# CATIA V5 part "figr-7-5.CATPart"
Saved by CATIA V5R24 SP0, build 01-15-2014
Part number: Part1
Bounding box of the stored display mesh (mm): x 0 to 95, y -20 to 20, z 0 to 40
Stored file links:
  D:\KAVITA\CATIA V5-6R2014 Project_ Kavita\CATIA V5-6R2014_partfiles\Partfiles\c07_catia_v5-6r2014_prt\figr-7-5.CATPart
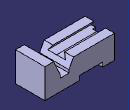
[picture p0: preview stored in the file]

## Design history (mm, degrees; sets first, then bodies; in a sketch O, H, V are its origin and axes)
Body1 (main body)
  Sketch1 on zx-plane, origin (0, 0, 0), H (-1, 0, 0), V (0, 0, 1)
    line L1 (0, 0) -> (-16, 0)
    line L2 (-16, 0) -> (-16, 6)
    line L3 (-16, 6) -> (-48, 6)
    line L4 (-48, 6) -> (-48, 0)
    point P4 (-48, 0)
    line L5 (-48, 0) -> (-95, 0)
    line L6 (-95, 0) -> (-95, 40)
    line L7 (-95, 40) -> (-83, 40)
    line L8 (-83, 40) -> (-74, 20)
    line L9 (-74, 20) -> (-74, 16)
    line L10 (-74, 16) -> (-62, 16)
    line L11 (-62, 16) -> (-62, 20)
    line L12 (-62, 20) -> (-56, 32)
    line L13 (-56, 32) -> (0, 32)
    line L14 (0, 32) -> (0, 0)
    length L1 = 16
    length L3 = 32
    length L13 = 56
    distance L14 L6 = 95
    length L14 = 32
    length L6 = 40
    length L12 H = 6
    length L10 = 12
    length L7 = 12
    length L9 = 4
    length L2 = 6
    distance L10 L5 = 16
    length L12 V = 12
    horizontal: L1 H, L3 H, L5 H, L7 H, L10 H, L13 H
    vertical: L2 V, L4 V, L6 V, L9 V, L11 V, L14 V
    coincidence: P4 H
  Pad1: profile Sketch1, direction (0, 1, 0), length 20, mirrored extent
  Sketch2 on face of Pad1, origin (0, 0, 0), H (0, -1, 0), V (0, 0, 1)
    axis line L1 (0, 0) -> (0, 40.9766)
    point P2 (0, 32)
    line L2 (0, 32) -> (-8, 32)
    point P3 (-8, 32)
    line L3 (-8, 32) -> (-12, 26)
    point P4 (-12, 26)
    line L4 (-12, 26) -> (0, 26)
    point P5 (0, 26)
    reference projected line E1 (-20, 32) -> (20, 32) from edge [face of Pad1 | face of Pad1]
    point P6 (0, 32)
    point P7 (8, 32)
    point P8 (12, 26)
    point P9 (0, 26)
    line L5 (0, 32) -> (8, 32)
    line L6 (8, 32) -> (12, 26)
    line L7 (12, 26) -> (0, 26)
    reference projected line E2 (-20, 0) -> (-20, 32) from edge [face of Pad1 | face of Pad1]
    reference projected line E3 (-20, 20) -> (-20, 40) from edge [face of Pad1 | face of Pad1]
    distance P4 E2 = 8
    length L3 V = 6
    distance P3 E3 = 12
    vertical: L1 V
    coincidence: P2 L1, P5 L1, L2 E1, P2 P6, P5 P9
    horizontal: L2 H, L4 H
    symmetry: P2 P6 L1, P3 P7 L1, P4 P8 L1, P5 P9 L1, L2 L5 L1, L3 L6 L1, L4 L7 L1
  Pocket1: profile Sketch2, direction (1, 0, 0), through (limit type 6)
  Sketch3 on face of Pad1, origin (0, 0, 0), H (0, -1, 0), V (0, 0, 1)
    line L1 (-6, 0) -> (6, 0)
    line L2 (6, 0) -> (6, 26)
    line L3 (6, 26) -> (-6, 26)
    line L4 (-6, 26) -> (-6, 0)
    reference projected line E1 (-12, 26) -> (0, 26) from edge [face of Pad1 | face of Pocket1]
    length L1 = 12
    horizontal: L1 H, L3 H
    vertical: L2 V, L4 V
    midpoint: O L1
    coincidence: L3 E1
  Pocket2: profile Sketch3, direction (1, 0, 0), length 4
  Sketch4 "Sketch.4" on face of Pad1, origin (0, 0, 40), H (1, 0, 0), V (0, 1, 0)
    line L1 (-12.5, -95) -> (12.5, -95)
    line L2 (12.5, -95) -> (12.5, -92)
    line L3 (12.5, -92) -> (-12.5, -92)
    line L4 (-12.5, -92) -> (-12.5, -95)
    reference projected line E1 (95, -20) -> (95, 20) from edge [face of Pad1 | face of Pad1]
    axis line L5 (0, 0) -> (0, -95)
    point P5 (0, -95)
    length L1 = 25
    length L2 = 3
    horizontal: L1 H, L3 H
    vertical: L2 V, L4 V, L5 V
    coincidence: L1 E1
    midpoint: P5 L1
